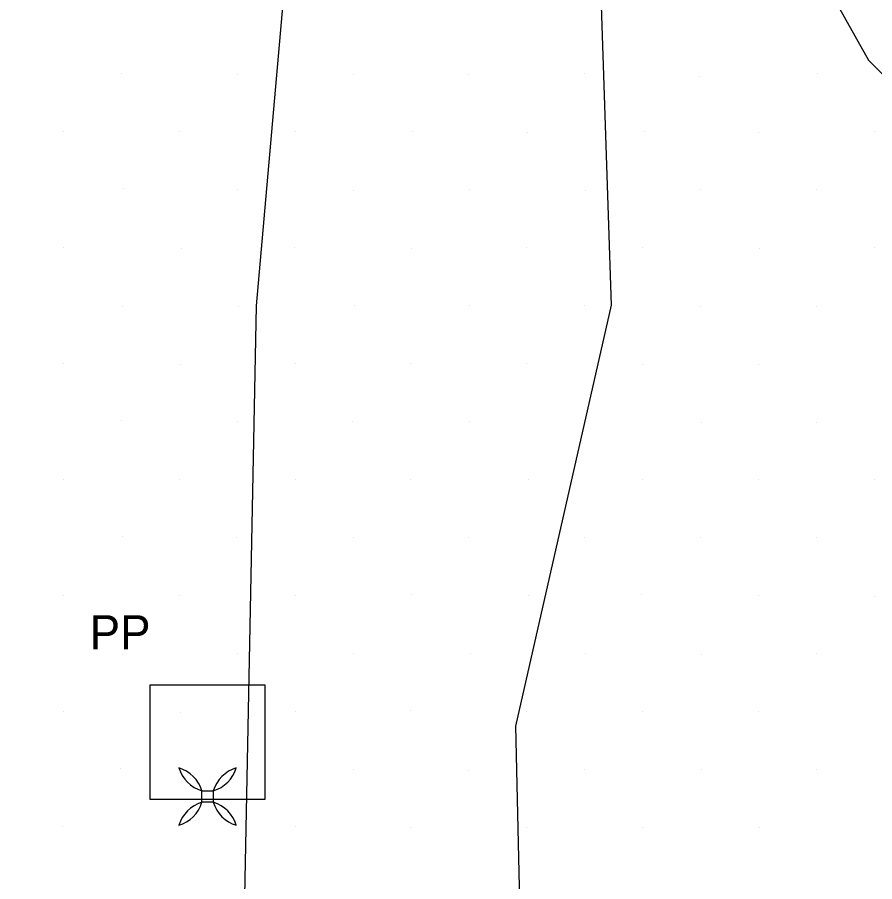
# Model space of a CAD drawing. Extents: x 1602514 to 1609837, y 863887 to 871157.
# Drawn here: x 1605561.4 to 1605718.4, y 866343.2 to 866501.5 of the extents above; entities that cross this region are included whole.
import ezdxf

# ---------------------------------------------------------------- set-up
doc = ezdxf.new("R2010")
doc.units = 0
for name, color, linetype in [('Photo-Anchor', 7, 'Continuous'), ('Survey-Ridge Lines', 7, 'Continuous'), ('Survey-Spot dirt', 7, 'Continuous'), ('Survey-Vegetation trees', 7, 'Continuous'), ('Utility-Pole', 7, 'Continuous')]:
    doc.layers.add(name, color=color, linetype=linetype)

msp = doc.modelspace()

# ---------------------------------------------------------------- linework, layer by layer
at = {"layer": 'Photo-Anchor'}
msp.add_lwpolyline([(1605595.22, 866359.88), (1605597.32, 866359.88), (1605597.32, 866357.78), (1605595.22, 866357.78)], close=True, dxfattribs=at)
msp.add_lwpolyline([(1605595.22, 866359.88), (1605597.32, 866359.88), (1605597.32, 866357.78), (1605595.22, 866357.78)], close=True, dxfattribs=at)
for centre, radius, start, end in [((1605589.21, 866358.07), 6.27, 16.7236, 73.2821), ((1605597.03, 866365.9), 6.29, 196.8106, 253.1951), ((1605589.21, 866358.07), 6.27, 16.7236, 73.2821), ((1605597.03, 866365.9), 6.29, 196.8106, 253.1951), ((1605603.32, 866358.07), 6.27, 106.7179, 163.2764), ((1605595.5, 866365.9), 6.29, 286.8049, 343.1894), ((1605603.32, 866358.07), 6.27, 106.7179, 163.2764), ((1605595.5, 866365.9), 6.29, 286.8049, 343.1894), ((1605589.21, 866359.58), 6.27, 286.7179, 343.2764), ((1605597.03, 866351.76), 6.29, 106.8049, 163.1894), ((1605589.21, 866359.58), 6.27, 286.7179, 343.2764), ((1605597.03, 866351.76), 6.29, 106.8049, 163.1894), ((1605603.32, 866359.58), 6.27, 196.7236, 253.2821), ((1605595.5, 866351.76), 6.29, 16.8106, 73.1951), ((1605603.32, 866359.58), 6.27, 196.7236, 253.2821), ((1605595.5, 866351.76), 6.29, 16.8106, 73.1951)]:
    msp.add_arc(centre, radius, start, end, dxfattribs=at)
at = {"layer": 'Survey-Ridge Lines'}
msp.add_lwpolyline([(1605600.14, 866596.02), (1605607.29, 866593.7), (1605631.22, 866573.69), (1605654.16, 866549.32), (1605677.5, 866528.06), (1605701.4, 866521.91), (1605717.28, 866493.64), (1605766.7, 866443.74), (1605793.99, 866437.12), (1605803.11, 866439.37), (1605811.92, 866436.39), (1605815.87, 866427.99), (1605811.61, 866419.75), (1605808.09, 866410.58), (1605810.57, 866401.61), (1605819.08, 866394.74), (1605831.26, 866384.39), (1605830.92, 866376.37), (1605833.24, 866370.35), (1605835.72, 866363.13), (1605836.92, 866350.02)], dxfattribs=at)
msp.add_lwpolyline([(1605600.14, 866596.02), (1605607.29, 866593.7), (1605631.22, 866573.69), (1605654.16, 866549.32), (1605677.5, 866528.06), (1605701.4, 866521.91), (1605717.28, 866493.64), (1605766.7, 866443.74), (1605793.99, 866437.12), (1605803.11, 866439.37), (1605811.92, 866436.39), (1605815.87, 866427.99), (1605811.61, 866419.75), (1605808.09, 866410.58), (1605810.57, 866401.61), (1605819.08, 866394.74), (1605831.26, 866384.39), (1605830.92, 866376.37), (1605833.24, 866370.35), (1605835.72, 866363.13), (1605836.92, 866350.02)], dxfattribs=at)
at = {"layer": 'Survey-Spot dirt'}
for p, q in [((1605580.48, 866491.16), (1605580.48, 866491.16)), ((1605580.48, 866491.16), (1605580.48, 866491.16)), ((1605601.69, 866491.02), (1605601.69, 866491.02)), ((1605601.69, 866491.02), (1605601.69, 866491.02)), ((1605623.03, 866490.99), (1605623.03, 866490.99)), ((1605623.03, 866490.99), (1605623.03, 866490.99)), ((1605644.05, 866491.02), (1605644.05, 866491.02)), ((1605644.05, 866491.02), (1605644.05, 866491.02)), ((1605665.28, 866491.1), (1605665.28, 866491.1)), ((1605665.28, 866491.1), (1605665.28, 866491.1)), ((1605707.87, 866491.13), (1605707.87, 866491.13)), ((1605707.87, 866491.13), (1605707.87, 866491.13)), ((1605686.28, 866490.63), (1605686.28, 866490.63)), ((1605686.28, 866490.63), (1605686.28, 866490.63)), ((1605569.81, 866480.5), (1605569.81, 866480.5)), ((1605569.81, 866480.5), (1605569.81, 866480.5)), ((1605591.15, 866480.49), (1605591.15, 866480.49)), ((1605591.15, 866480.49), (1605591.15, 866480.49)), ((1605612.35, 866480.53), (1605612.35, 866480.53)), ((1605612.35, 866480.53), (1605612.35, 866480.53)), ((1605633.7, 866480.5), (1605633.7, 866480.5)), ((1605633.7, 866480.5), (1605633.7, 866480.5)), ((1605654.93, 866480.35), (1605654.93, 866480.35)), ((1605654.93, 866480.35), (1605654.93, 866480.35)), ((1605676.22, 866480.53), (1605676.22, 866480.53)), ((1605676.22, 866480.53), (1605676.22, 866480.53)), ((1605697.23, 866480.39), (1605697.23, 866480.39)), ((1605697.23, 866480.39), (1605697.23, 866480.39)), ((1605718.3, 866480.5), (1605718.3, 866480.5)), ((1605718.3, 866480.5), (1605718.3, 866480.5)), ((1605580.87, 866470.07), (1605580.87, 866470.07)), ((1605580.87, 866470.07), (1605580.87, 866470.07)), ((1605601.76, 866469.88), (1605601.76, 866469.88)), ((1605601.76, 866469.88), (1605601.76, 866469.88)), ((1605623.03, 866469.83), (1605623.03, 866469.83)), ((1605623.03, 866469.83), (1605623.03, 866469.83)), ((1605644.23, 866469.94), (1605644.23, 866469.94)), ((1605644.23, 866469.94), (1605644.23, 866469.94)), ((1605665.49, 866469.74), (1605665.49, 866469.74)), ((1605665.49, 866469.74), (1605665.49, 866469.74)), ((1605686.54, 866469.87), (1605686.54, 866469.87)), ((1605686.54, 866469.87), (1605686.54, 866469.87)), ((1605707.82, 866469.91), (1605707.82, 866469.91)), ((1605707.82, 866469.91), (1605707.82, 866469.91)), ((1605569.97, 866459.31), (1605569.97, 866459.31)), ((1605569.97, 866459.31), (1605569.97, 866459.31)), ((1605591.42, 866459.2), (1605591.42, 866459.2)), ((1605591.42, 866459.2), (1605591.42, 866459.2)), ((1605612.27, 866459.33), (1605612.27, 866459.33)), ((1605612.27, 866459.33), (1605612.27, 866459.33)), ((1605633.65, 866459.15), (1605633.65, 866459.15)), ((1605633.65, 866459.15), (1605633.65, 866459.15)), ((1605654.72, 866459.25), (1605654.72, 866459.25)), ((1605654.72, 866459.25), (1605654.72, 866459.25)), ((1605675.93, 866459.24), (1605675.93, 866459.24)), ((1605675.93, 866459.24), (1605675.93, 866459.24)), ((1605697.25, 866459.14), (1605697.25, 866459.14)), ((1605697.25, 866459.14), (1605697.25, 866459.14)), ((1605718.41, 866459.3), (1605718.41, 866459.3)), ((1605718.41, 866459.3), (1605718.41, 866459.3)), ((1605580.6, 866448.58), (1605580.6, 866448.58)), ((1605580.6, 866448.58), (1605580.6, 866448.58)), ((1605601.88, 866448.46), (1605601.88, 866448.46)), ((1605601.88, 866448.46), (1605601.88, 866448.46)), ((1605623.08, 866448.75), (1605623.08, 866448.75)), ((1605623.08, 866448.75), (1605623.08, 866448.75)), ((1605644.2, 866448.62), (1605644.2, 866448.62)), ((1605644.2, 866448.62), (1605644.2, 866448.62)), ((1605665.34, 866448.73), (1605665.34, 866448.73)), ((1605665.34, 866448.73), (1605665.34, 866448.73)), ((1605686.5, 866448.61), (1605686.5, 866448.61)), ((1605686.5, 866448.61), (1605686.5, 866448.61)), ((1605707.83, 866448.59), (1605707.83, 866448.59)), ((1605707.83, 866448.59), (1605707.83, 866448.59)), ((1605569.82, 866438.08), (1605569.82, 866438.08)), ((1605569.82, 866438.08), (1605569.82, 866438.08)), ((1605591.26, 866437.9), (1605591.26, 866437.9)), ((1605591.26, 866437.9), (1605591.26, 866437.9)), ((1605612.32, 866438.05), (1605612.32, 866438.05)), ((1605612.32, 866438.05), (1605612.32, 866438.05)), ((1605633.39, 866438.09), (1605633.39, 866438.09)), ((1605633.39, 866438.09), (1605633.39, 866438.09)), ((1605654.65, 866438.02), (1605654.65, 866438.02)), ((1605654.65, 866438.02), (1605654.65, 866438.02)), ((1605675.94, 866437.99), (1605675.94, 866437.99)), ((1605675.94, 866437.99), (1605675.94, 866437.99)), ((1605697.17, 866437.97), (1605697.17, 866437.97)), ((1605697.17, 866437.97), (1605697.17, 866437.97)), ((1605580.56, 866427.67), (1605580.56, 866427.67)), ((1605580.56, 866427.67), (1605580.56, 866427.67)), ((1605601.68, 866427.46), (1605601.68, 866427.46)), ((1605601.68, 866427.46), (1605601.68, 866427.46)), ((1605622.88, 866427.41), (1605622.88, 866427.41)), ((1605622.88, 866427.41), (1605622.88, 866427.41)), ((1605644.21, 866427.4), (1605644.21, 866427.4)), ((1605644.21, 866427.4), (1605644.21, 866427.4)), ((1605665.3, 866427.37), (1605665.3, 866427.37)), ((1605665.3, 866427.37), (1605665.3, 866427.37)), ((1605686.68, 866427.37), (1605686.68, 866427.37)), ((1605686.68, 866427.37), (1605686.68, 866427.37)), ((1605707.74, 866427.38), (1605707.74, 866427.38)), ((1605707.74, 866427.38), (1605707.74, 866427.38)), ((1605569.89, 866416.84), (1605569.89, 866416.84)), ((1605569.89, 866416.84), (1605569.89, 866416.84)), ((1605591.11, 866416.81), (1605591.11, 866416.81)), ((1605591.11, 866416.81), (1605591.11, 866416.81)), ((1605612.33, 866416.85), (1605612.33, 866416.85)), ((1605612.33, 866416.85), (1605612.33, 866416.85)), ((1605633.43, 866416.87), (1605633.43, 866416.87)), ((1605633.43, 866416.87), (1605633.43, 866416.87)), ((1605654.96, 866416.91), (1605654.96, 866416.91)), ((1605654.96, 866416.91), (1605654.96, 866416.91)), ((1605675.91, 866416.85), (1605675.91, 866416.85)), ((1605675.91, 866416.85), (1605675.91, 866416.85)), ((1605697.2, 866416.78), (1605697.2, 866416.78)), ((1605697.2, 866416.78), (1605697.2, 866416.78)), ((1605718.36, 866416.85), (1605718.36, 866416.85)), ((1605718.36, 866416.85), (1605718.36, 866416.85)), ((1605580.63, 866406.46), (1605580.63, 866406.46)), ((1605580.63, 866406.46), (1605580.63, 866406.46)), ((1605601.65, 866406.2), (1605601.65, 866406.2)), ((1605601.65, 866406.2), (1605601.65, 866406.2)), ((1605622.91, 866406.16), (1605622.91, 866406.16)), ((1605622.91, 866406.16), (1605622.91, 866406.16)), ((1605644.11, 866406.18), (1605644.11, 866406.18)), ((1605644.11, 866406.18), (1605644.11, 866406.18)), ((1605665.28, 866406.27), (1605665.28, 866406.27)), ((1605665.28, 866406.27), (1605665.28, 866406.27)), ((1605686.53, 866406.28), (1605686.53, 866406.28)), ((1605686.53, 866406.28), (1605686.53, 866406.28)), ((1605707.72, 866406.22), (1605707.72, 866406.22)), ((1605707.72, 866406.22), (1605707.72, 866406.22)), ((1605569.85, 866395.67), (1605569.85, 866395.67)), ((1605569.85, 866395.67), (1605569.85, 866395.67)), ((1605591.16, 866395.65), (1605591.16, 866395.65)), ((1605591.16, 866395.65), (1605591.16, 866395.65)), ((1605612.28, 866395.56), (1605612.28, 866395.56)), ((1605612.28, 866395.56), (1605612.28, 866395.56)), ((1605633.57, 866395.85), (1605633.57, 866395.85)), ((1605633.57, 866395.85), (1605633.57, 866395.85)), ((1605654.96, 866395.7), (1605654.96, 866395.7)), ((1605654.96, 866395.7), (1605654.96, 866395.7)), ((1605675.8, 866395.74), (1605675.8, 866395.74)), ((1605675.8, 866395.74), (1605675.8, 866395.74)), ((1605697.11, 866395.68), (1605697.11, 866395.68)), ((1605697.11, 866395.68), (1605697.11, 866395.68)), ((1605718.4, 866395.37), (1605718.4, 866395.37)), ((1605718.4, 866395.37), (1605718.4, 866395.37)), ((1605601.79, 866385.06), (1605601.79, 866385.06)), ((1605601.79, 866385.06), (1605601.79, 866385.06)), ((1605622.9, 866385), (1605622.9, 866385)), ((1605622.9, 866385), (1605622.9, 866385)), ((1605644.32, 866385.02), (1605644.32, 866385.02)), ((1605644.32, 866385.02), (1605644.32, 866385.02)), ((1605707.69, 866384.98), (1605707.69, 866384.98)), ((1605707.69, 866384.98), (1605707.69, 866384.98)), ((1605580.73, 866384.88), (1605580.73, 866384.88)), ((1605580.73, 866384.88), (1605580.73, 866384.88)), ((1605665.4, 866384.94), (1605665.4, 866384.94)), ((1605665.4, 866384.94), (1605665.4, 866384.94)), ((1605686.75, 866384.85), (1605686.75, 866384.85)), ((1605686.75, 866384.85), (1605686.75, 866384.85)), ((1605569.91, 866374.46), (1605569.91, 866374.46)), ((1605569.91, 866374.46), (1605569.91, 866374.46)), ((1605591.29, 866374.3), (1605591.29, 866374.3)), ((1605591.29, 866374.3), (1605591.29, 866374.3)), ((1605612.29, 866374.33), (1605612.29, 866374.33)), ((1605612.29, 866374.33), (1605612.29, 866374.33)), ((1605633.48, 866374.66), (1605633.48, 866374.66)), ((1605633.48, 866374.66), (1605633.48, 866374.66)), ((1605654.75, 866374.47), (1605654.75, 866374.47)), ((1605654.75, 866374.47), (1605654.75, 866374.47)), ((1605675.91, 866374.36), (1605675.91, 866374.36)), ((1605675.91, 866374.36), (1605675.91, 866374.36)), ((1605697.1, 866374.41), (1605697.1, 866374.41)), ((1605697.1, 866374.41), (1605697.1, 866374.41)), ((1605580.4, 866363.9), (1605580.4, 866363.9)), ((1605580.4, 866363.9), (1605580.4, 866363.9)), ((1605601.58, 866363.96), (1605601.58, 866363.96)), ((1605601.58, 866363.96), (1605601.58, 866363.96)), ((1605622.9, 866363.81), (1605622.9, 866363.81)), ((1605622.9, 866363.81), (1605622.9, 866363.81)), ((1605644.13, 866363.68), (1605644.13, 866363.68)), ((1605644.13, 866363.68), (1605644.13, 866363.68)), ((1605665.37, 866363.87), (1605665.37, 866363.87)), ((1605665.37, 866363.87), (1605665.37, 866363.87)), ((1605686.63, 866363.79), (1605686.63, 866363.79)), ((1605686.63, 866363.79), (1605686.63, 866363.79)), ((1605707.79, 866363.82), (1605707.79, 866363.82)), ((1605707.79, 866363.82), (1605707.79, 866363.82)), ((1605569.78, 866353.34), (1605569.78, 866353.34)), ((1605569.78, 866353.34), (1605569.78, 866353.34)), ((1605591, 866353.26), (1605591, 866353.26)), ((1605591, 866353.26), (1605591, 866353.26)), ((1605612.3, 866353.27), (1605612.3, 866353.27)), ((1605612.3, 866353.27), (1605612.3, 866353.27)), ((1605633.44, 866353.23), (1605633.44, 866353.23)), ((1605633.44, 866353.23), (1605633.44, 866353.23)), ((1605654.57, 866353.25), (1605654.57, 866353.25)), ((1605654.57, 866353.25), (1605654.57, 866353.25)), ((1605675.85, 866353.2), (1605675.85, 866353.2)), ((1605675.85, 866353.2), (1605675.85, 866353.2)), ((1605697.39, 866353.08), (1605697.39, 866353.08)), ((1605697.39, 866353.08), (1605697.39, 866353.08))]:
    msp.add_line(p, q, dxfattribs=at)
at = {"layer": 'Survey-Vegetation trees'}
for points in [[(1605601.79, 866275.83), (1605605.2, 866448.65), (1605612.42, 866530.39), (1605609.93, 866556.1), (1605459.73, 866746.47), (1605424.26, 866753.41), (1605387.87, 866745.45), (1605328.37, 866764.72), (1605298.66, 866722.79), (1605306.28, 866699.16), (1605277.32, 866658.75), (1605265.13, 866625.97), (1605217.79, 866602.88), (1605158.36, 866628.8), (1605148.45, 866592.97), (1605247.5, 866507.58), (1605323.27, 866431.24), (1605384.81, 866367.9), (1605438.61, 866328.19), (1605473.87, 866349.1), (1605499.88, 866323.66)], [(1605601.79, 866275.83), (1605605.2, 866448.65), (1605612.42, 866530.39), (1605609.93, 866556.1), (1605459.73, 866746.47), (1605424.26, 866753.41), (1605387.87, 866745.45), (1605328.37, 866764.72), (1605298.66, 866722.79), (1605306.28, 866699.16), (1605277.32, 866658.75), (1605265.13, 866625.97), (1605217.79, 866602.88), (1605158.36, 866628.8), (1605148.45, 866592.97), (1605247.5, 866507.58), (1605323.27, 866431.24), (1605384.81, 866367.9), (1605438.61, 866328.19), (1605473.87, 866349.1), (1605499.88, 866323.66)], [(1605933.61, 866558.21), (1605731.71, 866735.08), (1605563.24, 866712.42), (1605565.76, 866669.83), (1605667.1, 866540.23), (1605670.14, 866448.74), (1605652.62, 866371.74), (1605654.91, 866272.63), (1605846.15, 866251.29), (1605868.24, 866270.35), (1605917, 866264.25)], [(1605933.61, 866558.21), (1605731.71, 866735.08), (1605563.24, 866712.42), (1605565.76, 866669.83), (1605667.1, 866540.23), (1605670.14, 866448.74), (1605652.62, 866371.74), (1605654.91, 866272.63), (1605846.15, 866251.29), (1605868.24, 866270.35), (1605917, 866264.25)]]:
    msp.add_lwpolyline(points, dxfattribs=at)
at = {"layer": 'Utility-Pole'}
msp.add_lwpolyline([(1605585.74, 866379.3), (1605606.75, 866379.3), (1605606.75, 866358.3), (1605585.74, 866358.3)], close=True, dxfattribs=at)
msp.add_lwpolyline([(1605585.74, 866379.3), (1605606.75, 866379.3), (1605606.75, 866358.3), (1605585.74, 866358.3)], close=True, dxfattribs=at)

# ---------------------------------------------------------------- texts
msp.add_text('PP', height=6.251, dxfattribs=at).set_placement((1605574.68, 866385.77))
msp.add_text('PP', height=6.251, dxfattribs=at).set_placement((1605574.68, 866385.77))

doc.saveas('drawing.dxf')
